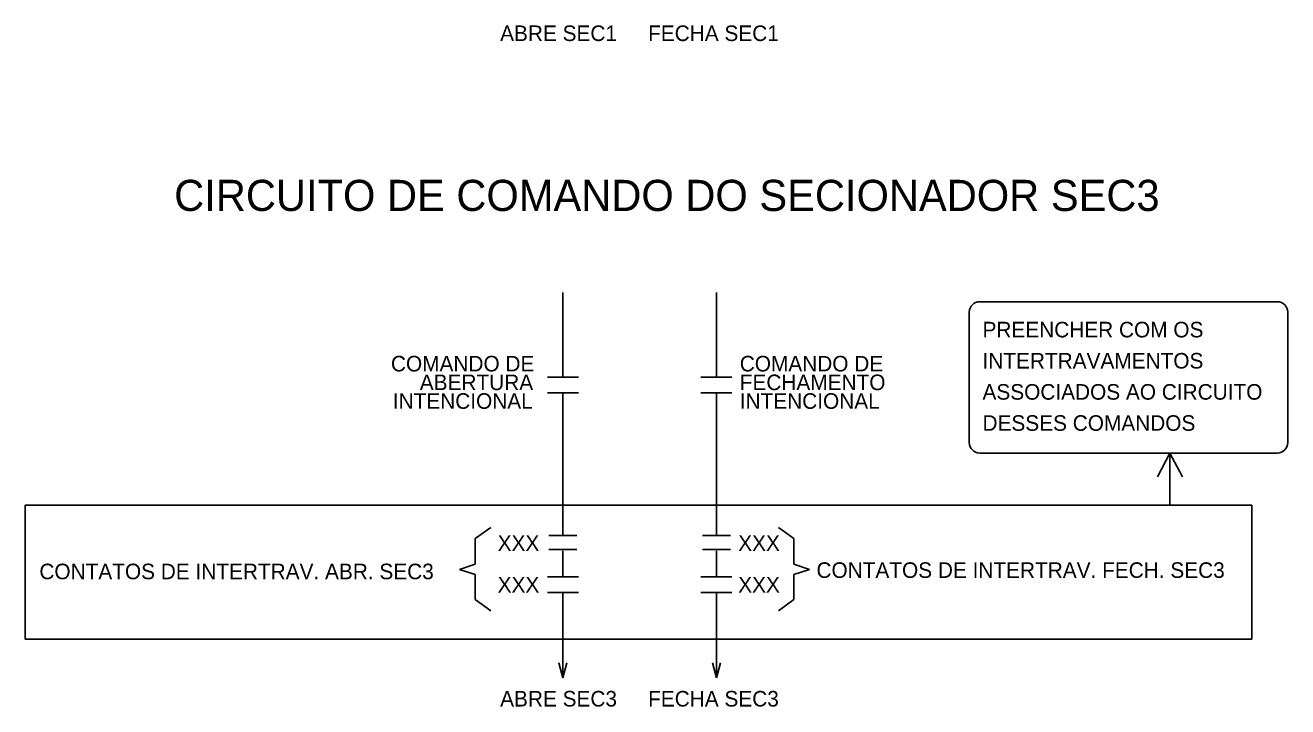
# Model space of a CAD drawing. Extents: x 400 to 1404, y 358 to 952.
# Drawn here: x 1111 to 1232.7, y 429.3 to 495 of the extents above; entities that cross this region are included whole.
import ezdxf

# ---------------------------------------------------------------- set-up
doc = ezdxf.new("R2010")
doc.units = 0
doc.layers.add('New Level (0)', color=7, linetype='Continuous')

msp = doc.modelspace()

# ---------------------------------------------------------------- linework, layer by layer
for p, q in [((1162.82, 469.25), (1162.82, 461.08)), ((1177.61, 469.25), (1177.61, 461.08)), ((1164.32, 461.08), (1161.32, 461.08)), ((1176.11, 461.08), (1179.11, 461.08)), ((1164.32, 459.58), (1161.32, 459.58)), ((1162.82, 459.58), (1162.82, 445.84)), ((1176.11, 459.58), (1179.11, 459.58)), ((1177.61, 459.58), (1177.61, 445.84)), ((1154.36, 445.52), (1155.86, 446.6)), ((1185.08, 445.52), (1183.58, 446.6)), ((1154.36, 443.06), (1154.36, 445.52)), ((1164.17, 445.84), (1161.47, 445.84)), ((1176.26, 445.84), (1178.96, 445.84)), ((1185.08, 443.06), (1185.08, 445.52)), ((1161.47, 444.49), (1164.17, 444.49)), ((1162.82, 444.34), (1162.82, 441.83)), ((1178.96, 444.49), (1176.26, 444.49)), ((1177.61, 444.34), (1177.61, 441.83)), ((1152.86, 442.56), (1154.36, 443.06)), ((1186.58, 442.56), (1185.08, 443.06)), ((1152.86, 442.56), (1154.36, 442.06)), ((1154.36, 442.06), (1154.36, 439.65)), ((1164.32, 441.83), (1161.32, 441.83)), ((1176.11, 441.83), (1179.11, 441.83)), ((1186.58, 442.56), (1185.08, 442.06)), ((1185.08, 442.06), (1185.08, 439.65)), ((1154.36, 439.65), (1155.86, 438.57)), ((1164.32, 440.33), (1161.32, 440.33)), ((1162.82, 440.33), (1162.82, 432.1)), ((1176.11, 440.33), (1179.11, 440.33)), ((1177.61, 440.33), (1177.61, 432.1)), ((1185.08, 439.65), (1183.58, 438.57)), ((1162.82, 432.1), (1162.43, 433.55)), ((1162.82, 432.1), (1163.21, 433.55)), ((1177.61, 432.1), (1177.22, 433.55)), ((1177.61, 432.1), (1178, 433.55))]:
    msp.add_line(p, q)
at = {"layer": 'New Level (0)'}
for p, q in [((1201.98, 454.77), (1201.98, 467.35)), ((1202.98, 468.35), (1231.66, 468.35)), ((1232.66, 467.35), (1232.66, 454.77)), ((1231.66, 453.77), (1202.98, 453.77)), ((1221.31, 453.77), (1220.1, 451.47)), ((1221.31, 448.74), (1221.31, 453.77)), ((1221.31, 453.77), (1222.52, 451.47))]:
    msp.add_line(p, q, dxfattribs=at)
msp.add_lwpolyline([(1111.01, 448.74), (1229.2, 448.74), (1229.2, 435.85), (1111.01, 435.85)], close=True, dxfattribs=at)
for centre, start, end in [((1202.98, 467.35), 90, 180), ((1231.66, 467.35), 0, 90), ((1202.98, 454.77), 180, 270), ((1231.66, 454.77), 270, 0)]:
    msp.add_arc(centre, 1, start, end, dxfattribs=at)

# ---------------------------------------------------------------- texts
for s, height, p in [('ABRE SEC1', 1.5, (1156.77, 493.46)), ('FECHA SEC1', 1.5, (1171.03, 493.46)), ('CIRCUITO DE COMANDO DO SECIONADOR SEC3', 3, (1125.36, 477.09)), ('PREENCHER COM OS ', 1.5, (1203.25, 464.91)), ('COMANDO DE', 1.5, (1146.25, 461.63)), ('COMANDO DE ', 1.5, (1179.86, 461.63)), ('INTERTRAVAMENTOS', 1.5, (1203.25, 461.91)), (' ABERTURA', 1.5, (1148.47, 459.83)), ('FECHAMENTO ', 1.5, (1179.86, 459.83)), ('ASSOCIADOS AO CIRCUITO ', 1.5, (1203.25, 458.91)), (' INTENCIONAL', 1.5, (1145.87, 458.03)), ('INTENCIONAL', 1.5, (1179.86, 458.03)), ('DESSES COMANDOS', 1.5, (1203.25, 455.91)), ('XXX', 1.5, (1156.53, 444.34)), ('XXX', 1.5, (1179.71, 444.34)), ('CONTATOS DE INTERTRAV. ABR. SEC3', 1.5, (1112.37, 441.61)), ('CONTATOS DE INTERTRAV. FECH. SEC3', 1.5, (1187.25, 441.74)), ('XXX', 1.5, (1156.53, 440.33)), ('XXX', 1.5, (1179.71, 440.33)), ('ABRE SEC3', 1.5, (1156.77, 429.35)), ('FECHA SEC3', 1.5, (1171.03, 429.35))]:
    msp.add_text(s, height=height).set_placement(p)

doc.saveas('drawing.dxf')
